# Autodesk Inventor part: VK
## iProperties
Created: 2004-01
Part Number: VK
Material: Aluminium - 6061
Document SubType Name: Modellieren
Designer: Ulrich
Control State: 0
Master: False
Checked Out: False
Shininess: 20.0
Angle Display Precision: 2
Document Length Units: 11269
Document Angle Units: 11279
Document Time Units: 11290
Document Mass Units: 11283
Document Length Units Precision: 3
Document Angle Units Precision: 2
Density: 0.0
Volumn: 0.0
Area: 0.0
PropertySet Name: Model Information
Author: Ulrich
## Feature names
1. Grundkörper [Extrusion]
2. Gewinde [Hole]
